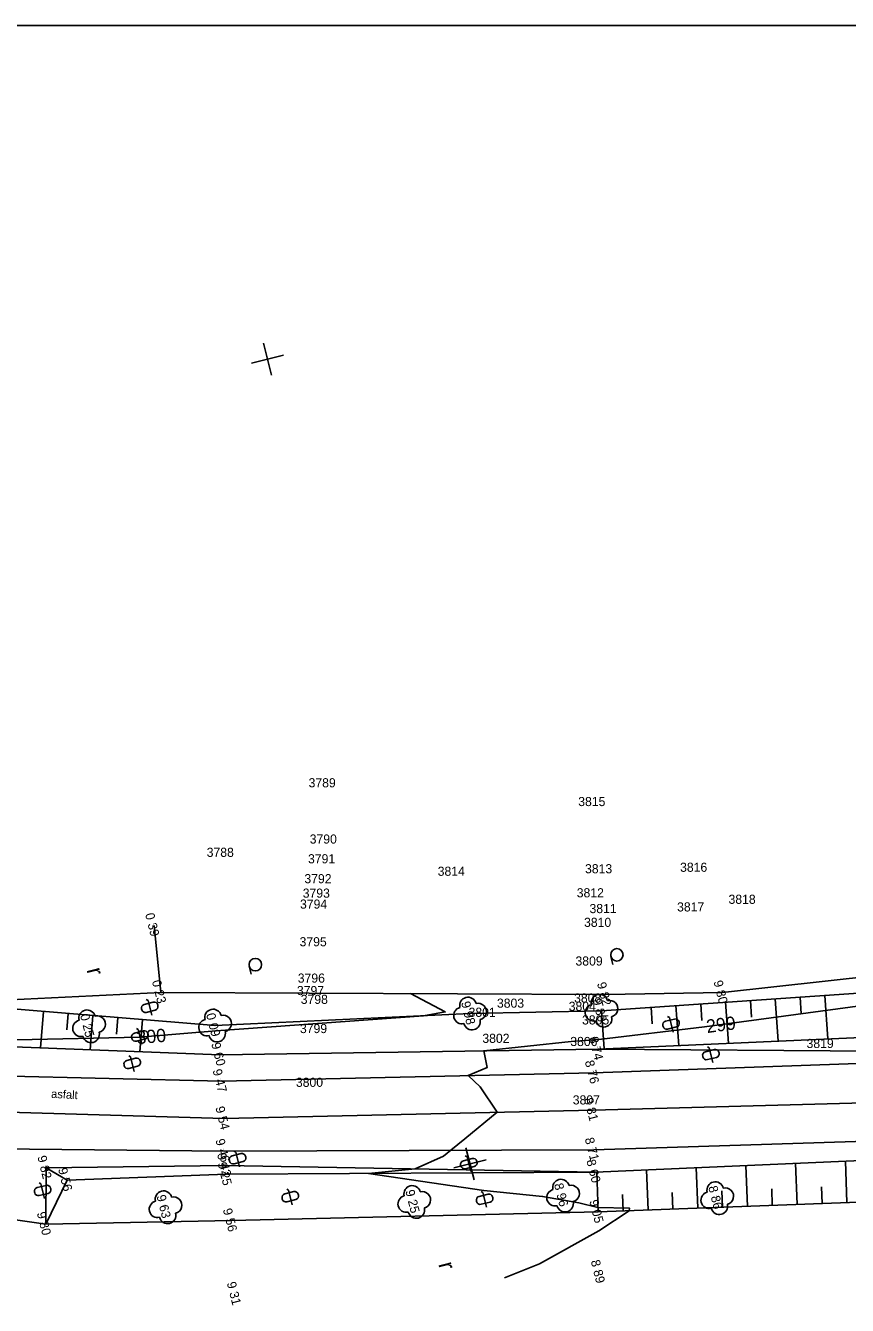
# Model space of a CAD drawing. Extents: x -740053 to -737517, y -1033516 to -1032488.
# Drawn here: x -739248 to -739198.5, y -1032583.6 to -1032506.5 of the extents above; entities that cross this region are included whole.
import ezdxf

# ---------------------------------------------------------------- set-up
doc = ezdxf.new("R2010")
doc.units = 0
for name, color, linetype in [('bod-cislo', 7, 'Continuous'), ('bod-oznac', 7, 'Continuous'), ('bod-vyska', 7, 'Continuous'), ('bod-vyska100', 7, 'Continuous'), ('Contours', 7, 'Continuous'), ('Contours highlighted', 7, 'Continuous'), ('Contours text', 7, 'Continuous'), ('ctv-sit', 7, 'Continuous'), ('nazvy-bud-povr', 7, 'Continuous'), ('osa-komunikace', 7, 'Continuous'), ('ploty', 7, 'Continuous'), ('Predmety bez rozlišeni', 7, 'Continuous'), ('rozhraní kultůr', 7, 'Continuous'), ('silnice', 7, 'Continuous'), ('Technické šrafy', 7, 'Continuous'), ('Terenni-hrana', 7, 'Continuous'), ('Znacky-kultury', 7, 'Continuous')]:
    doc.layers.add(name, color=color, linetype=linetype)

# ---------------------------------------------------------------- blocks, each defined once
blk = doc.blocks.new('POINT_DISPLAY')
blk.add_line((0, 0), (0, 0))
blk = doc.blocks.new('p_strom')
for centre, start, end in [((0, 1), 0, 180), ((-1, 0), 90, 270), ((1, 0), 270, 90), ((0, -1), 180, 0)]:
    blk.add_arc(centre, 1, start, end)
at = {"rotation": -180}
blk.add_blockref('POINT_DISPLAY', (0, 0), dxfattribs=at)
blk = doc.blocks.new('p_orna')
blk.add_text('r', height=2).set_placement((0, 0))
blk = doc.blocks.new('p_neplod')
for p, q in [((-0.82, 0), (-0.99, -0.18)), ((1, 0), (-0.82, 0)), ((-0.49, 0.56), (-0.49, -0.55)), ((0.05, 1.01), (-0.04, 1.01)), ((0.5, -0.55), (0.5, 0.56)), ((-0.04, -1), (0.05, -1))]:
    blk.add_line(p, q)
for centre, start, end in [((-0.04, 0.56), 90, 180), ((0.05, 0.56), 0, 90), ((-0.04, -0.55), 180, 270), ((0.05, -0.55), 270, 0)]:
    blk.add_arc(centre, 0.45, start, end)
blk = doc.blocks.new('p_zahr')
blk.add_line((0, -0.75), (0.99, -0.75))
blk.add_circle((0, 0), 0.75)
blk = doc.blocks.new('ctvsit')
for p, q in [((0, -2), (0, 2)), ((2, 0), (-2, 0))]:
    blk.add_line(p, q)

msp = doc.modelspace()

# ---------------------------------------------------------------- linework, layer by layer
at = {"layer": 'Contours'}
msp.add_lwpolyline([(-739219.147, -1032581.947), (-739217.041, -1032581.093), (-739213.462, -1032579.104), (-739211.634, -1032577.898), (-739211.602, -1032577.75), (-739213.509, -1032577.7), (-739214.67, -1032577.422), (-739216.851, -1032577.039), (-739220.382, -1032576.674), (-739227.348, -1032575.649), (-739224.526, -1032575.369), (-739222.818, -1032574.611), (-739222.371, -1032574.257), (-739221.544, -1032573.57), (-739219.594, -1032571.962), (-739220.612, -1032570.428), (-739221.343, -1032569.752), (-739220.192, -1032569.272), (-739220.391, -1032568.26), (-739215.124, -1032567.705), (-739213.454, -1032567.587), (-739207.093, -1032566.812), (-739196.811, -1032565.432)], dxfattribs=at)
at = {"layer": 'Contours highlighted'}
msp.add_lwpolyline([(-739253.192, -1032567.705), (-739241.147, -1032567.445), (-739236.534, -1032567.062), (-739224.017, -1032566.145), (-739222.713, -1032565.912), (-739224.806, -1032564.808)], dxfattribs=at)
at = {"layer": 'osa-komunikace'}
for p, q in [((-739254.613, -1032571.789), (-739236.036, -1032572.341)), ((-739236.036, -1032572.341), (-739213.808, -1032571.829)), ((-739213.808, -1032571.829), (-739195.02, -1032571.338))]:
    msp.add_line(p, q, dxfattribs=at)
at = {"layer": 'ploty'}
for p, q in [((-739240.266, -1032560.701), (-739239.856, -1032564.744)), ((-739206.001, -1032564.749), (-739196.631, -1032563.71)), ((-739239.856, -1032564.744), (-739213.027, -1032564.857)), ((-739213.027, -1032564.857), (-739206.001, -1032564.749))]:
    msp.add_line(p, q, dxfattribs=at)
at = {"layer": 'Predmety bez rozlišeni'}
for p, q in [((-739304.249, -1032506.478), (-739199.249, -1032506.478)), ((-739199.249, -1032506.478), (-739094.249, -1032506.478))]:
    msp.add_line(p, q, dxfattribs=at)
at = {"layer": 'rozhraní kultůr'}
msp.add_line((-739252.923, -1032565.393), (-739239.856, -1032564.744), dxfattribs=at)
at = {"layer": 'silnice'}
for p, q in [((-739213.756, -1032569.578), (-739195.262, -1032568.944)), ((-739254.624, -1032569.658), (-739236.2, -1032570.093)), ((-739236.2, -1032570.093), (-739213.756, -1032569.578)), ((-739254.228, -1032574.136), (-739236.028, -1032574.298)), ((-739213.761, -1032574.23), (-739194.745, -1032573.619)), ((-739236.028, -1032574.298), (-739213.761, -1032574.23))]:
    msp.add_line(p, q, dxfattribs=at)
at = {"layer": 'Technické šrafy'}
for p, q in [((-739210.301, -1032565.638), (-739210.233, -1032566.636)), ((-739208.805, -1032565.536), (-739208.641, -1032567.94)), ((-739207.308, -1032565.434), (-739207.24, -1032566.432)), ((-739205.812, -1032565.332), (-739205.643, -1032567.808)), ((-739204.315, -1032565.23), (-739204.247, -1032566.228)), ((-739202.819, -1032565.128), (-739202.645, -1032567.676)), ((-739201.322, -1032565.026), (-739201.254, -1032566.024)), ((-739199.826, -1032564.924), (-739199.647, -1032567.545)), ((-739246.943, -1032565.885), (-739247.125, -1032568.09)), ((-739245.448, -1032566.008), (-739245.53, -1032567.005)), ((-739243.953, -1032566.131), (-739244.124, -1032568.204)), ((-739242.458, -1032566.254), (-739242.54, -1032567.251)), ((-739240.963, -1032566.377), (-739241.123, -1032568.319)), ((-739213.294, -1032565.843), (-739213.138, -1032568.138)), ((-739198.501, -1032577.411), (-739198.594, -1032574.906)), ((-739213.49, -1032577.967), (-739213.58, -1032575.563)), ((-739210.492, -1032577.856), (-739210.582, -1032575.431)), ((-739207.494, -1032577.745), (-739207.585, -1032575.3)), ((-739204.497, -1032577.633), (-739204.588, -1032575.168)), ((-739201.499, -1032577.522), (-739201.591, -1032575.037)), ((-739200, -1032577.466), (-739200.037, -1032576.467)), ((-739211.991, -1032577.912), (-739212.028, -1032576.912)), ((-739208.993, -1032577.8), (-739209.031, -1032576.801)), ((-739205.995, -1032577.689), (-739206.033, -1032576.69)), ((-739202.998, -1032577.578), (-739203.035, -1032576.578))]:
    msp.add_line(p, q, dxfattribs=at)
at = {"layer": 'Terenni-hrana'}
for p, q in [((-739213.294, -1032565.843), (-739197.226, -1032564.747)), ((-739252.923, -1032565.393), (-739236.591, -1032566.737)), ((-739236.591, -1032566.737), (-739221.223, -1032566.013)), ((-739221.223, -1032566.013), (-739213.294, -1032565.843)), ((-739254.272, -1032567.816), (-739236.28, -1032568.504)), ((-739213.506, -1032568.154), (-739195.638, -1032567.368)), ((-739236.28, -1032568.504), (-739213.506, -1032568.154)), ((-739195.445, -1032568.299), (-739213.506, -1032568.154)), ((-739213.662, -1032575.566), (-739194.762, -1032574.737)), ((-739246.799, -1032578.701), (-739246.766, -1032575.31)), ((-739246.766, -1032575.31), (-739235.934, -1032575.162)), ((-739246.766, -1032575.31), (-739245.518, -1032576.048)), ((-739235.934, -1032575.162), (-739213.662, -1032575.566)), ((-739235.902, -1032575.7), (-739213.662, -1032575.566)), ((-739246.799, -1032578.701), (-739245.518, -1032576.048)), ((-739245.518, -1032576.048), (-739235.902, -1032575.7)), ((-739252.874, -1032577.838), (-739246.799, -1032578.701)), ((-739235.582, -1032578.486), (-739213.49, -1032577.967)), ((-739213.49, -1032577.967), (-739194.559, -1032577.264)), ((-739246.799, -1032578.701), (-739235.582, -1032578.486))]:
    msp.add_line(p, q, dxfattribs=at)

# ---------------------------------------------------------------- block references
at = {"layer": 'bod-oznac', "rotation": -75.86979040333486}
for p in [(-739240.266, -1032560.701), (-739239.856, -1032564.744), (-739213.027, -1032564.857), (-739206.001, -1032564.749), (-739221.223, -1032566.013), (-739213.294, -1032565.843), (-739244.189, -1032566.783), (-739236.591, -1032566.737), (-739236.28, -1032568.504), (-739213.506, -1032568.154), (-739236.2, -1032570.093), (-739213.756, -1032569.578), (-739213.808, -1032571.829), (-739236.036, -1032572.341), (-739236.028, -1032574.298), (-739213.761, -1032574.23), (-739246.766, -1032575.31), (-739235.934, -1032575.162), (-739213.662, -1032575.566), (-739245.518, -1032576.048), (-739235.902, -1032575.7), (-739215.614, -1032576.986), (-739206.315, -1032577.141), (-739239.578, -1032577.687), (-739224.582, -1032577.367), (-739213.49, -1032577.967), (-739246.799, -1032578.701), (-739235.582, -1032578.486), (-739213.399, -1032581.605), (-739235.344, -1032582.912)]:
    msp.add_blockref('POINT_DISPLAY', p, dxfattribs=at)
at = {"layer": 'ctv-sit', "xscale": 0.49999999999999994, "yscale": 0.5, "rotation": 104.13020959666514}
for p in [(-739233.429, -1032526.58), (-739221.222, -1032575.067)]:
    msp.add_blockref('ctvsit', p, dxfattribs=at)
at = {"layer": 'Znacky-kultury', "xscale": 0.49999999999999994}
for name, p, yscale, rotation in [('p_zahr', (-739212.366, -1032562.479), 0.5, -75.86979040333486), ('p_orna', (-739244.343, -1032563.366), 0.5, -75.86979040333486), ('p_zahr', (-739234.165, -1032563.066), 0.5, -75.86979040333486), ('p_strom', (-739221.223, -1032566.013), 0.4999999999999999, -75.86979040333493), ('p_strom', (-739213.294, -1032565.843), 0.4999999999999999, -75.86979040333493), ('p_strom', (-739244.189, -1032566.783), 0.4999999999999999, -75.86979040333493), ('p_neplod', (-739240.536, -1032565.635), 0.5, -75.86979040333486), ('p_strom', (-739236.591, -1032566.737), 0.4999999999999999, -75.86979040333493), ('p_neplod', (-739209.105, -1032566.65), 0.5, -75.86979040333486), ('p_neplod', (-739241.129, -1032567.365), 0.5, -75.86979040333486), ('p_neplod', (-739206.704, -1032568.483), 0.5, -75.86979040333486), ('p_neplod', (-739241.592, -1032569.012), 0.5, -75.86979040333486), ('p_neplod', (-739235.239, -1032574.761), 0.5, -75.86979040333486), ('p_neplod', (-739221.299, -1032575.055), 0.5, -75.86979040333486), ('p_neplod', (-739246.99, -1032576.675), 0.5, -75.86979040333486), ('p_neplod', (-739232.061, -1032577.05), 0.5, -75.86979040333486), ('p_strom', (-739224.582, -1032577.367), 0.4999999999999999, -75.86979040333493), ('p_strom', (-739215.614, -1032576.986), 0.4999999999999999, -75.86979040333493), ('p_strom', (-739206.315, -1032577.141), 0.4999999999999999, -75.86979040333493), ('p_strom', (-739239.578, -1032577.687), 0.4999999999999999, -75.86979040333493), ('p_neplod', (-739220.347, -1032577.201), 0.5, -75.86979040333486), ('p_orna', (-739223.141, -1032581.103), 0.5, -75.86979040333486)]:
    msp.add_blockref(name, p, dxfattribs=dict(at, yscale=yscale, rotation=rotation))

# ---------------------------------------------------------------- texts
at = {"layer": 'bod-cislo'}
for s, p in [('3789', (-739230.955, -1032552.383)), ('3815', (-739214.698, -1032553.513)), ('3790', (-739230.888, -1032555.773)), ('3788', (-739237.098, -1032556.573)), ('3791', (-739230.989, -1032556.963)), ('3814', (-739223.171, -1032557.713)), ('3813', (-739214.288, -1032557.563)), ('3816', (-739208.558, -1032557.473)), ('3792', (-739231.208, -1032558.163)), ('3793', (-739231.308, -1032559.033)), ('3812', (-739214.788, -1032559.013)), ('3794', (-739231.471, -1032559.693)), ('3811', (-739214.019, -1032559.963)), ('3817', (-739208.738, -1032559.863)), ('3818', (-739205.638, -1032559.403)), ('3810', (-739214.348, -1032560.793)), ('3795', (-739231.498, -1032561.963)), ('3809', (-739214.865, -1032563.123)), ('3796', (-739231.608, -1032564.153)), ('3797', (-739231.658, -1032564.903)), ('3798', (-739231.428, -1032565.433)), ('3808', (-739214.948, -1032565.353)), ('3801', (-739221.309, -1032566.213)), ('3803', (-739219.598, -1032565.663)), ('3804', (-739215.271, -1032565.853)), ('3805', (-739214.468, -1032566.673)), ('3799', (-739231.475, -1032567.193)), ('3802', (-739220.478, -1032567.783)), ('3806', (-739215.178, -1032567.973)), ('3819', (-739200.935, -1032568.093)), ('3800', (-739231.718, -1032570.433)), ('3807', (-739215.028, -1032571.493))]:
    msp.add_text(s, height=0.55, dxfattribs=at).set_placement(p)
at = {"layer": 'bod-vyska'}
for s, p in [('0 39', (-739240.814, -1032560.026)), ('0 23', (-739240.404, -1032564.068)), ('9 82', (-739213.572, -1032564.195)), ('9 80', (-739206.546, -1032564.086)), ('9 98', (-739221.768, -1032565.35)), ('9 80', (-739213.839, -1032565.18)), ('0 25', (-739244.738, -1032566.108)), ('0 09', (-739237.139, -1032566.061)), ('9 60', (-739236.828, -1032567.829)), ('8 74', (-739214.055, -1032567.479)), ('9 47', (-739236.745, -1032569.43)), ('8 76', (-739214.305, -1032568.903)), ('9 54', (-739236.581, -1032571.678)), ('8 81', (-739214.357, -1032571.154)), ('9 46', (-739236.573, -1032573.635)), ('8 71', (-739214.309, -1032573.555)), ('9 82', (-739247.311, -1032574.647)), ('9 42', (-739236.479, -1032574.499)), ('8 60', (-739214.213, -1032574.878)), ('9 56', (-739246.063, -1032575.385)), ('9 25', (-739236.447, -1032575.037)), ('8 96', (-739216.162, -1032576.31)), ('8 86', (-739206.863, -1032576.465)), ('9 63', (-739240.126, -1032577.012)), ('9 25', (-739225.127, -1032576.704)), ('9 05', (-739214.035, -1032577.304)), ('9 80', (-739247.344, -1032578.038)), ('9 56', (-739236.127, -1032577.823)), ('8 89', (-739213.948, -1032580.93)), ('9 31', (-739235.889, -1032582.249))]:
    msp.add_text(s, height=0.55, rotation=284.13021, dxfattribs=at).set_placement(p)
at = {"layer": 'bod-vyska100'}
for s, p in [('300 39', (-739240.339, -1032560.548)), ('300 23', (-739239.929, -1032564.59)), ('299 82', (-739213.1, -1032564.705)), ('299 80', (-739206.073, -1032564.596)), ('299 98', (-739221.295, -1032565.861)), ('299 80', (-739213.367, -1032565.69)), ('300 25', (-739244.263, -1032566.63)), ('300 09', (-739236.664, -1032566.583)), ('299 60', (-739236.353, -1032568.351)), ('298 74', (-739213.58, -1032568)), ('298 76', (-739213.829, -1032569.425)), ('299 47', (-739236.273, -1032569.94)), ('298 81', (-739213.882, -1032571.675)), ('299 54', (-739236.109, -1032572.188)), ('299 46', (-739236.101, -1032574.146)), ('298 71', (-739213.834, -1032574.076)), ('299 82', (-739246.839, -1032575.158)), ('299 42', (-739236.007, -1032575.009)), ('299 25', (-739235.975, -1032575.547)), ('298 60', (-739213.735, -1032575.411)), ('299 56', (-739245.591, -1032575.895)), ('299 25', (-739224.655, -1032577.214)), ('298 96', (-739215.687, -1032576.832)), ('298 86', (-739206.388, -1032576.987)), ('299 63', (-739239.651, -1032577.534)), ('299 05', (-739213.563, -1032577.815)), ('299 80', (-739246.872, -1032578.548)), ('299 56', (-739235.655, -1032578.333)), ('298 89', (-739213.473, -1032581.451)), ('299 31', (-739235.417, -1032582.759))]:
    msp.add_text(s, height=0.05, rotation=284.13021, dxfattribs=at).set_placement(p)
at = {"layer": 'Contours text'}
for s, rotation, p in [('299', 7.64325, (-739206.926, -1032567.193)), ('300', 4.75477, (-739241.297, -1032567.859))]:
    msp.add_text(s, height=0.8, rotation=rotation, dxfattribs=at).set_placement(p)
at = {"layer": 'nazvy-bud-povr'}
msp.add_text('asfalt', height=0.5, rotation=357.12292, dxfattribs=at).set_placement((-739246.484, -1032571.093))

doc.saveas('drawing.dxf')
